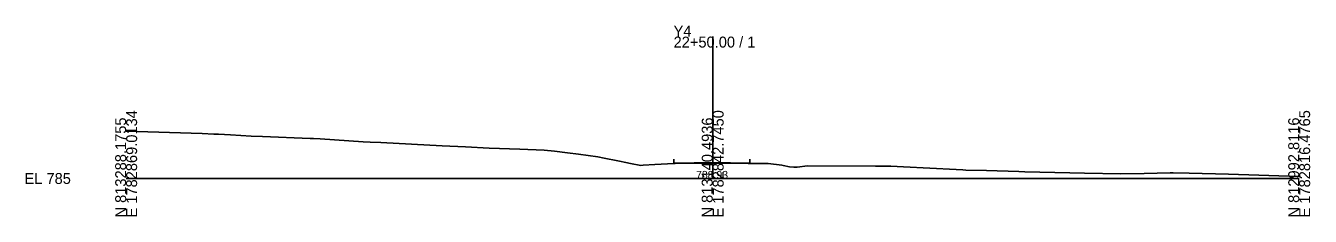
# Model space of a CAD drawing. Extents: x -26 to 3903, y -10 to 9562.
# Drawn here: x 974.3 to 1302.8, y 4990.3 to 5039.1 of the extents above; entities that cross this region are included whole.
import ezdxf

# ---------------------------------------------------------------- set-up
doc = ezdxf.new("R2010")
doc.units = 0
for name, color, linetype in [('Exist Cross Section Cell', 7, 'Continuous'), ('Exist XS Center Line Elevation Label', 7, 'Continuous'), ('Exist XS Ground Line', 7, 'Continuous'), ('Prop XS EOT Tick Mark', 7, 'Continuous'), ('Prop XS Finish Grade Pavement', 7, 'Continuous')]:
    doc.layers.add(name, color=color, linetype=linetype)

msp = doc.modelspace()

# ---------------------------------------------------------------- linework, layer by layer
at = {"layer": 'Exist Cross Section Cell'}
for p, q in [((1150, 5000), (1150, 5036.31)), ((1000, 5000), (1150, 5000)), ((1150, 5000), (1300, 5000))]:
    msp.add_line(p, q, dxfattribs=at)
at = {"layer": 'Exist XS Ground Line'}
for p, q in [((1000, 5012.1), (1019.43, 5011.51)), ((1019.43, 5011.51), (1022.46, 5011.33)), ((1022.46, 5011.33), (1023.59, 5011.33)), ((1023.59, 5011.33), (1026.65, 5011.19)), ((1026.65, 5011.19), (1031.97, 5010.84)), ((1031.97, 5010.84), (1034.9, 5010.73)), ((1034.9, 5010.73), (1047.07, 5010.27)), ((1047.07, 5010.27), (1047.92, 5010.23)), ((1047.92, 5010.23), (1049.6, 5010.12)), ((1049.6, 5010.12), (1060.58, 5009.42)), ((1060.58, 5009.42), (1062.43, 5009.33)), ((1062.43, 5009.33), (1065.12, 5009.19)), ((1065.12, 5009.19), (1080.78, 5008.37)), ((1080.78, 5008.37), (1086.81, 5008.06)), ((1086.81, 5008.06), (1092.83, 5007.73)), ((1092.83, 5007.73), (1100.69, 5007.51)), ((1100.69, 5007.51), (1106.88, 5007.27)), ((1106.88, 5007.27), (1109.52, 5007.01)), ((1109.52, 5007.01), (1112.87, 5006.55)), ((1112.87, 5006.55), (1115.71, 5006.26)), ((1115.71, 5006.26), (1120.63, 5005.5)), ((1120.63, 5005.5), (1122.27, 5005.23)), ((1122.27, 5005.23), (1125.77, 5004.53)), ((1125.77, 5004.53), (1128.22, 5004.01)), ((1128.22, 5004.01), (1128.57, 5003.92)), ((1128.57, 5003.92), (1128.98, 5003.83)), ((1128.98, 5003.83), (1131.59, 5003.33)), ((1132.24, 5003.37), (1135.22, 5003.61)), ((1135.22, 5003.61), (1140.04, 5003.8)), ((1140.04, 5003.8), (1140.37, 5003.81)), ((1140.37, 5003.81), (1150.01, 5003.93)), ((1150.01, 5003.93), (1159.06, 5003.81)), ((1159.06, 5003.81), (1159.46, 5003.81)), ((1159.46, 5003.81), (1164.22, 5003.85)), ((1164.22, 5003.85), (1167.71, 5003.4)), ((1131.59, 5003.33), (1132.24, 5003.37)), ((1167.71, 5003.4), (1168.06, 5003.33)), ((1168.06, 5003.33), (1169.62, 5002.96)), ((1169.62, 5002.96), (1170.77, 5002.85)), ((1170.77, 5002.85), (1171.58, 5002.91)), ((1171.58, 5002.91), (1174.22, 5003.23)), ((1174.22, 5003.23), (1191.63, 5003.11)), ((1191.63, 5003.11), (1195.59, 5003.15)), ((1195.59, 5003.15), (1198.79, 5002.95)), ((1198.79, 5002.95), (1212.27, 5002.31)), ((1212.27, 5002.31), (1213.98, 5002.18)), ((1213.98, 5002.18), (1214.75, 5002.15)), ((1214.75, 5002.15), (1220.03, 5002.01)), ((1220.03, 5002.01), (1228.29, 5001.79)), ((1228.29, 5001.79), (1229.79, 5001.74)), ((1229.79, 5001.74), (1241.37, 5001.4)), ((1241.37, 5001.4), (1245.1, 5001.34)), ((1245.1, 5001.34), (1254.37, 5001.19)), ((1254.37, 5001.19), (1260.35, 5001.23)), ((1260.35, 5001.23), (1267.04, 5001.45)), ((1267.04, 5001.45), (1267.74, 5001.44)), ((1267.74, 5001.44), (1271.85, 5001.38)), ((1271.85, 5001.38), (1281.92, 5001.1)), ((1281.92, 5001.1), (1300, 5000.53))]:
    msp.add_line(p, q, dxfattribs=at)
at = {"layer": 'Prop XS EOT Tick Mark'}
for p, q in [((1140.05, 5003.93), (1140.05, 5004.93)), ((1159.48, 5003.93), (1159.48, 5004.93))]:
    msp.add_line(p, q, dxfattribs=at)
at = {"layer": 'Prop XS Finish Grade Pavement'}
for p, q in [((1140.05, 5003.93), (1140.37, 5003.93)), ((1140.37, 5003.93), (1150.01, 5004.05)), ((1150.01, 5004.05), (1159.07, 5003.94)), ((1159.07, 5003.94), (1159.48, 5003.93))]:
    msp.add_line(p, q, dxfattribs=at)

# ---------------------------------------------------------------- texts
at = {"layer": 'Exist Cross Section Cell'}
for s, p in [('Y4', (1140, 5036.31)), ('22+50.00 / 1', (1140, 5033.51)), ('EL 785', (974, 4998.6))]:
    msp.add_text(s, height=2.8, dxfattribs=at).set_placement(p)
for s, p in [('E 1782869.0134', (1002.8, 4990)), ('E 1782842.7450', (1152.8, 4990)), ('E 1782816.4765', (1302.8, 4990)), ('N 813288.1755', (1000, 4990)), ('N 813140.4936', (1150, 4990)), ('N 812992.8116', (1300, 4990))]:
    msp.add_text(s, height=2.8, rotation=90, dxfattribs=at).set_placement(p)
at = {"layer": 'Exist XS Center Line Elevation Label'}
msp.add_text('788.93', height=2, dxfattribs=at).set_placement((1145.75, 4999.93))

doc.saveas('drawing.dxf')
